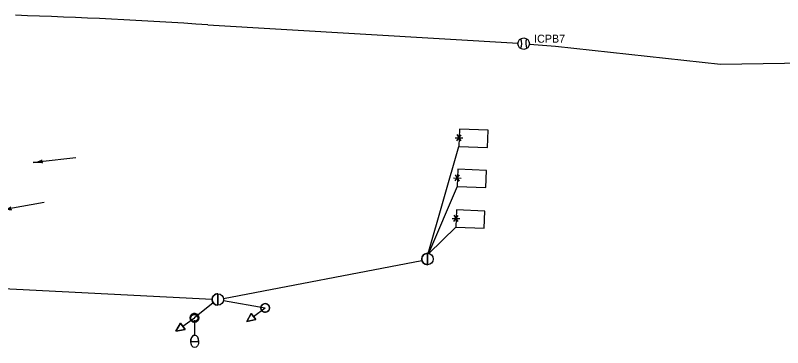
# Model space of a CAD drawing. Extents: x 596176 to 605330, y 332416 to 402398.
# Drawn here: x 604328.3 to 604596.7, y 349880.3 to 349996.7 of the extents above; entities that cross this region are included whole.
import ezdxf

# ---------------------------------------------------------------- set-up
doc = ezdxf.new("R2010")
doc.units = 0
for name, color, linetype in [('P_LTG', 7, 'Continuous'), ('P_SIG', 7, 'Continuous'), ('P_SIG_Conduit', 7, 'Continuous'), ('P_SIG_IC', 7, 'Continuous'), ('P_SIG_Loops', 7, 'Continuous')]:
    doc.layers.add(name, color=color, linetype=linetype)

# ---------------------------------------------------------------- blocks, each defined once
blk = doc.blocks.new('_U244')
at = {"layer": 'P_SIG'}
blk.add_circle((0, 0), 0.116, dxfattribs=at)
for start, end in [(0, 180), (180, 0)]:
    blk.add_arc((0, 0), 0.116, start, end, dxfattribs=at)
blk = doc.blocks.new('_U257')
at = {"layer": 'P_SIG_Loops'}
for p, q in [((-0.055, -0.084), (0.052, 0.081)), ((0.056, -0.083), (-0.053, 0.082)), ((-0.105, -0.001), (0.099, -0.001))]:
    blk.add_line(p, q, dxfattribs=at)
blk.add_lwpolyline([(0, -0.229), (0.762, -0.229), (0.762, 0.229), (0, 0.229)], close=True, dxfattribs=at)
blk = doc.blocks.new('_U211')
at = {"layer": 'P_SIG'}
blk.add_line((0.03, 6.11), (-0.03, -6.09), dxfattribs=at)
blk.add_lwpolyline([(-0.03, -6.09), (0.03, 6.11)], dxfattribs=at)
blk.add_circle((0, 0.01), 6.1, dxfattribs=at)
for start, end in [(89.70079, 180), (180, 269.70079)]:
    blk.add_arc((0, 0.01), 6.1, start, end, dxfattribs=at)
blk = doc.blocks.new('_U260')
at = {"layer": 'P_SIG'}
blk.add_line((-0.385, 0.001), (0, 0), dxfattribs=at)
for points in [[(-0.611, 0.001), (-0.385, 0.101), (-0.385, -0.1), (-0.611, 0.001)], [(-0.385, 0.101), (-0.611, 0.001), (-0.385, -0.1), (-0.385, 0.101)], [(-0.611, 0.001), (-0.385, 0.101), (-0.385, -0.1), (-0.611, 0.001)]]:
    blk.add_lwpolyline(points, dxfattribs=at)
blk = doc.blocks.new('_U269')
at = {"layer": 'P_SIG'}
blk.add_line((-0.017, -0.02), (-0.975, -0.02), dxfattribs=at)
blk.add_lwpolyline([(-0.914, 0.018), (-0.975, -0.02), (-0.914, -0.058)], dxfattribs=at)
for centre, start, end in [((-1.158, 0.78), 270, 287.7623), ((-1.158, -0.819), 72.2377, 90)]:
    blk.add_arc(centre, 0.799, start, end, dxfattribs=at)
blk = doc.blocks.new('LUMINAIRES_1')
at = {"layer": 'P_LTG'}
for p, q in [((4.32, 25.12), (-4.14, 25.12)), ((0.05, 2.3), (0.05, 18.44))]:
    blk.add_line(p, q, dxfattribs=at)
blk.add_circle((0.05, 0.15), 3.68, dxfattribs=at)
blk.add_ellipse((0.09, 25.12), major_axis=(0, 6.65), ratio=0.636439, dxfattribs=at)
blk.add_ellipse((0.09, 25.12), major_axis=(0, 6.65), ratio=0.636439, start_param=1.570796, end_param=4.712389, dxfattribs=at)
blk = doc.blocks.new('_U212')
at = {"layer": 'P_SIG'}
blk.add_circle((0, 0.01), 6.1, dxfattribs=at)
for centre, start, end in [((-15.46, 0.12), 336.67411, 22.52722), ((15.45, 0.15), 157.57508, 203.4282)]:
    blk.add_arc(centre, 13.28, start, end, dxfattribs=at)

msp = doc.modelspace()

# ---------------------------------------------------------------- linework, layer by layer
at = {"layer": 'P_SIG_Conduit'}
for points in [[(604401.07, 349897.59), (604470.52, 349910.9)], [(604292.01, 349902.73), (604397.1, 349897.32)], [(604397.53, 349895.98), (604390.91, 349890.76)], [(604401.07, 349896.86), (604415.67, 349894.24)]]:
    msp.add_lwpolyline(points, dxfattribs=at)
at = {"layer": 'P_SIG_IC'}
for points in [[(604395.62, 349993.39), (604504.11, 349986.94)], [(604508.1, 349986.64), (604517.18, 349985.97), (604574.92, 349979.61), (604641.97, 349980.69)]]:
    msp.add_lwpolyline(points, dxfattribs=at)
msp.add_arc((604273.73, 348210.05), 1787.5, 86.08988, 88.25122, dxfattribs=at)
at = {"layer": 'P_SIG_Loops'}
for points in [[(604472.66, 349913.35), (604483.41, 349950.83)], [(604482.82, 349936.79), (604472.74, 349913.35)], [(604482.31, 349922.57), (604472.95, 349913.3)]]:
    msp.add_lwpolyline(points, dxfattribs=at)

# ---------------------------------------------------------------- block references
at = {"layer": 'P_LTG', "xscale": 0.3280833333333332, "yscale": 0.32808333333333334, "rotation": -179.14755096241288}
msp.add_blockref('LUMINAIRES_1', (604390.91, 349890.76), dxfattribs=at)
at = {"layer": 'P_SIG'}
for name, p, xscale, yscale, rotation in [('_U269', (604349.62, 349947.05), 13.123333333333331, 13.123333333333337, 6.188674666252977), ('_U269', (604338.54, 349931.52), 13.123333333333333, 13.123333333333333, 10.52994057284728), ('_U260', (604415.67, 349894.24), 13.12333333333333, 13.123333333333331, 36.23789948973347), ('_U244', (604415.67, 349894.24), 13.123333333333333, 13.123333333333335, 36.20208107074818), ('_U260', (604390.93, 349890.78), 13.12333333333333, 13.123333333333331, 36.23789948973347), ('_U244', (604390.95, 349890.79), 13.123333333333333, 13.123333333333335, 36.20208107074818)]:
    msp.add_blockref(name, p, dxfattribs=dict(at, xscale=xscale, yscale=yscale, rotation=rotation))
at = {"layer": 'P_SIG_Conduit', "xscale": 0.32808333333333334, "yscale": 0.32808333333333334}
for p in [(604472.47, 349911.36), (604399.1, 349897.21)]:
    msp.add_blockref('_U211', p, dxfattribs=at)
at = {"layer": 'P_SIG_IC', "xscale": 0.32808333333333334, "yscale": 0.32808333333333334}
msp.add_blockref('_U212', (604506.1, 349986.78), dxfattribs=at)
at = {"layer": 'P_SIG_Loops', "xscale": 13.123333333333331, "yscale": 13.123333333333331, "rotation": -2.222040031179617}
for p in [(604483.52, 349953.83), (604482.92, 349939.79), (604482.43, 349925.57)]:
    msp.add_blockref('_U257', p, dxfattribs=at)

# ---------------------------------------------------------------- texts
at = {"layer": 'P_SIG_IC'}
msp.add_text('ICPB7', height=2.8, dxfattribs=at).set_placement((604509.75, 349987.13))

doc.saveas('drawing.dxf')
